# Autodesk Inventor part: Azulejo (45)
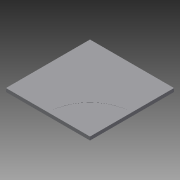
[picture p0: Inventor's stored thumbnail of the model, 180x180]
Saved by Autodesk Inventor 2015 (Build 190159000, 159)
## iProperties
Created: 2015-04
Part Number: Azulejo (45)
Material: Genérico
Document SubType Name: Modeling
Designer: Felipe
Density: 1 g/cm^3
Appearance: Padrão
Author: Felipe
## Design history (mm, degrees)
sketch "Sketch1"
  geometry: L1 (-5999.978, 1162.687)-(-5915.126, 1162.687); L2 (6980.022, 1162.687)-(6895.169, 1162.687); L3 (-1034.12, -6357.313)-(-1063.775, -6417.313); L4 (-5519.978, 1582.687)-(-6306.841, 1582.687); L5 (-2499.978, 5642.687)-(-1019.978, 5642.687); L6 (5000.022, -4857.313)-(6000.022, -4857.313); L7 (6000.022, -4857.313)-(6000.022, -6277.313); L8 (6000.022, -4837.313)-(5000.022, -4837.313); L9 (5000.022, -4837.313)-(5000.022, -3357.313); L10 (5000.022, -3357.313)-(6000.022, -3357.313); L11 (6000.022, -3357.313)-(6000.022, -4837.313); L12 (6000.022, -3337.313)-(5000.022, -3337.313); L13 (5000.022, -3337.313)-(5000.022, -1857.313); L14 (5000.022, -1857.313)-(6000.022, -1857.313); L15 (6000.022, -1857.313)-(6000.022, -3337.313); L16 (6000.022, -1837.313)-(5000.022, -1837.313); L17 (5000.022, -1837.313)-(5000.022, -357.313); L18 (5000.022, -357.313)-(6000.022, -357.313); L19 (6000.022, -357.313)-(6000.022, -1837.313); L20 (4000.022, -4837.313)-(3500.022, -4837.313); L21 (3500.022, -4837.313)-(3500.022, -3357.313); L22 (3500.022, -3357.313)-(4000.022, -3357.313); L23 (4000.022, -3357.313)-(4000.022, -4837.313); L24 (4000.022, -3337.313)-(3500.022, -3337.313); L25 (3500.022, -3337.313)-(3500.022, -1857.313); L26 (2000.022, 2662.687)-(2480.022, 2662.687); L27 (500.022, 2662.687)-(1980.022, 2662.687); L28 (-999.978, 2662.687)-(480.022, 2662.687); L29 (3500.022, -1857.313)-(4000.022, -1857.313); L30 (4000.022, -1857.313)-(4000.022, -3337.313); L31 (4000.022, -1837.313)-(3500.022, -1837.313); L32 (3500.022, -1837.313)-(3500.022, -357.313); L33 (3500.022, -357.313)-(4000.022, -357.313); L34 (4000.022, -357.313)-(4000.022, -1837.313); L35 (-5519.978, 1142.687)-(-5519.978, -337.313); L36 (6500.022, 2662.687)-(6500.022, 4142.687); L37 (6500.022, -337.313)-(6500.022, 1142.687); L38 (6480.022, 4162.687)-(5173.227, 4162.687); L39 (5000.022, 4142.687)-(6480.022, 4142.687); L40 (6480.022, 4142.687)-(6480.022, 2662.687); L41 (6480.022, 2662.687)-(5000.022, 2662.687); L42 (5000.022, 2662.687)-(5000.022, 4142.687); L43 (5000.022, 2642.687)-(6480.022, 2642.687); L44 (6480.022, 1142.687)-(6480.022, -337.313); L45 (6480.022, -337.313)-(5000.022, -337.313); L46 (5000.022, -337.313)-(5000.022, 1142.687); L47 (7965.922, 4162.687)-(6500.022, 4162.687); L48 (7965.922, 2662.687)-(6500.022, 2662.687); L49 (6500.022, 4142.687)-(7965.922, 4142.687); L50 (6500.022, 2642.687)-(7965.922, 2642.687); L51 (4980.022, 4162.687)-(3500.022, 4162.687); L52 (3500.022, 4142.687)-(4980.022, 4142.687); L53 (4980.022, 4142.687)-(4980.022, 2662.687); L54 (4980.022, 2662.687)-(3500.022, 2662.687); L55 (3500.022, 2662.687)-(3500.022, 4142.687); L56 (3500.022, 2642.687)-(4980.022, 2642.687); L57 (4980.022, 1142.687)-(4980.022, -337.313); L58 (4980.022, -337.313)-(3500.022, -337.313); L59 (3500.022, -337.313)-(3500.022, 1142.687); L60 (3500.022, -1837.313)-(3500.022, -357.313); L61 (3500.022, -3337.313)-(3500.022, -1857.313); L62 (3500.022, -4837.313)-(3500.022, -3357.313); L63 (3500.022, -6257.313)-(3500.022, -4857.313); L64 (3306.817, 4162.687)-(2000.022, 4162.687)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; A1 r 750 centre (-1009.978, 5652.687) between (-1759.912, 5642.687) and (-1019.978, 4902.754); A2 r 750 centre (-1009.978, 5652.687) between (-999.978, 4902.754) and (-260.045, 5642.687); A3 r 750 centre (-1009.978, 5652.687) between (-260.045, 5662.687) and (-999.978, 6402.621); A4 r 750 centre (-1009.978, 5652.687) between (-1019.978, 6402.621) and (-1759.912, 5662.687); 4 further points
  constraints: 1922 end point, 104 point on line, 8 point on circle, 4 centre point, 2 other
extrude "Extrusion1" new body sketch "Sketch1" distance "d0" = 60; taper "d1" = 0 deg
extrude "Extrusion2" new body sketch "Sketch1" distance "d2" = 60; taper "d3" = 0 deg
body "Solid1"
body "Solid2"
